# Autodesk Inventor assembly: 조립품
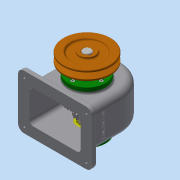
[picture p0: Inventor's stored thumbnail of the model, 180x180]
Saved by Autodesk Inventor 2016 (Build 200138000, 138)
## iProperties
Created: 2018-11
Part Number: 조립품
Material: 일반
Document SubType Name: Assembly
Designer: 공506_40
Author: 공506_40
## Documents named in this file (14)
- C:\Users\공506_40\Desktop\481111V1010\조립품.iam
- C:\Users\공506_40\Desktop\481111V1010\V-벨트풀리.ipt
- C:\Users\공506_40\Desktop\481111V1010\뒤커버.ipt
- C:\Users\공506_40\Desktop\481111V1010\멈춤나사 M4.ipt
- C:\Users\공506_40\Desktop\481111V1010\베어링 6203.ipt
- C:\Users\공506_40\Desktop\481111V1010\본체.ipt
- C:\Users\공506_40\Desktop\481111V1010\볼트 M4.ipt
- C:\Users\공506_40\Desktop\481111V1010\부시.ipt
- C:\Users\공506_40\Desktop\481111V1010\스퍼기어.ipt
- C:\Users\공506_40\Desktop\481111V1010\앞커버.ipt
- C:\Users\공506_40\Desktop\481111V1010\오일 실 28 40 8.ipt
- C:\Users\공506_40\Desktop\481111V1010\축.ipt
- C:\Users\공506_40\Desktop\481111V1010\키 5x5x18.ipt
- C:\Users\공506_40\Desktop\481111V1010\키 6x6x22.ipt
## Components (1 placed, 1 different names)
1. V-벨트풀리:1
